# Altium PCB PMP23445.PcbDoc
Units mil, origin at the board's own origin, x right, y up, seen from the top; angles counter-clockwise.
Board outline 2350 x 1450 mil, 2 copper layers (Top Layer, Bottom Layer), stack 62 mil thick; 36 components, 16 nets, 69 pads, 11 vias.
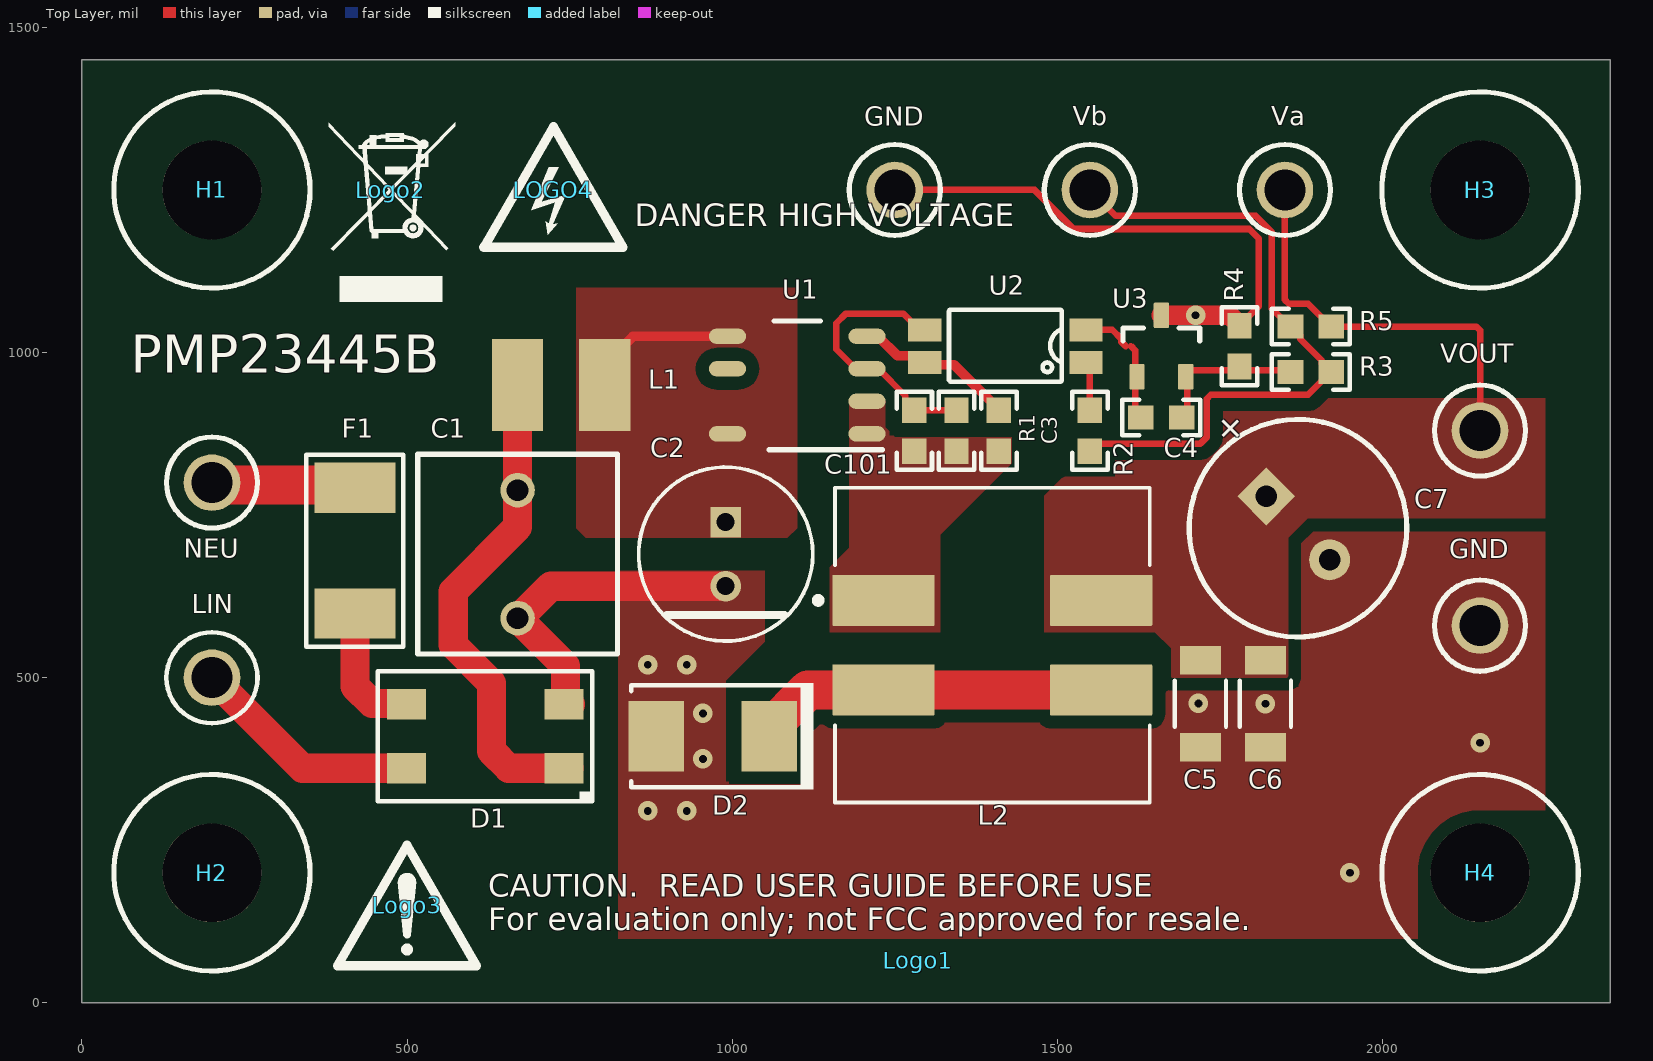
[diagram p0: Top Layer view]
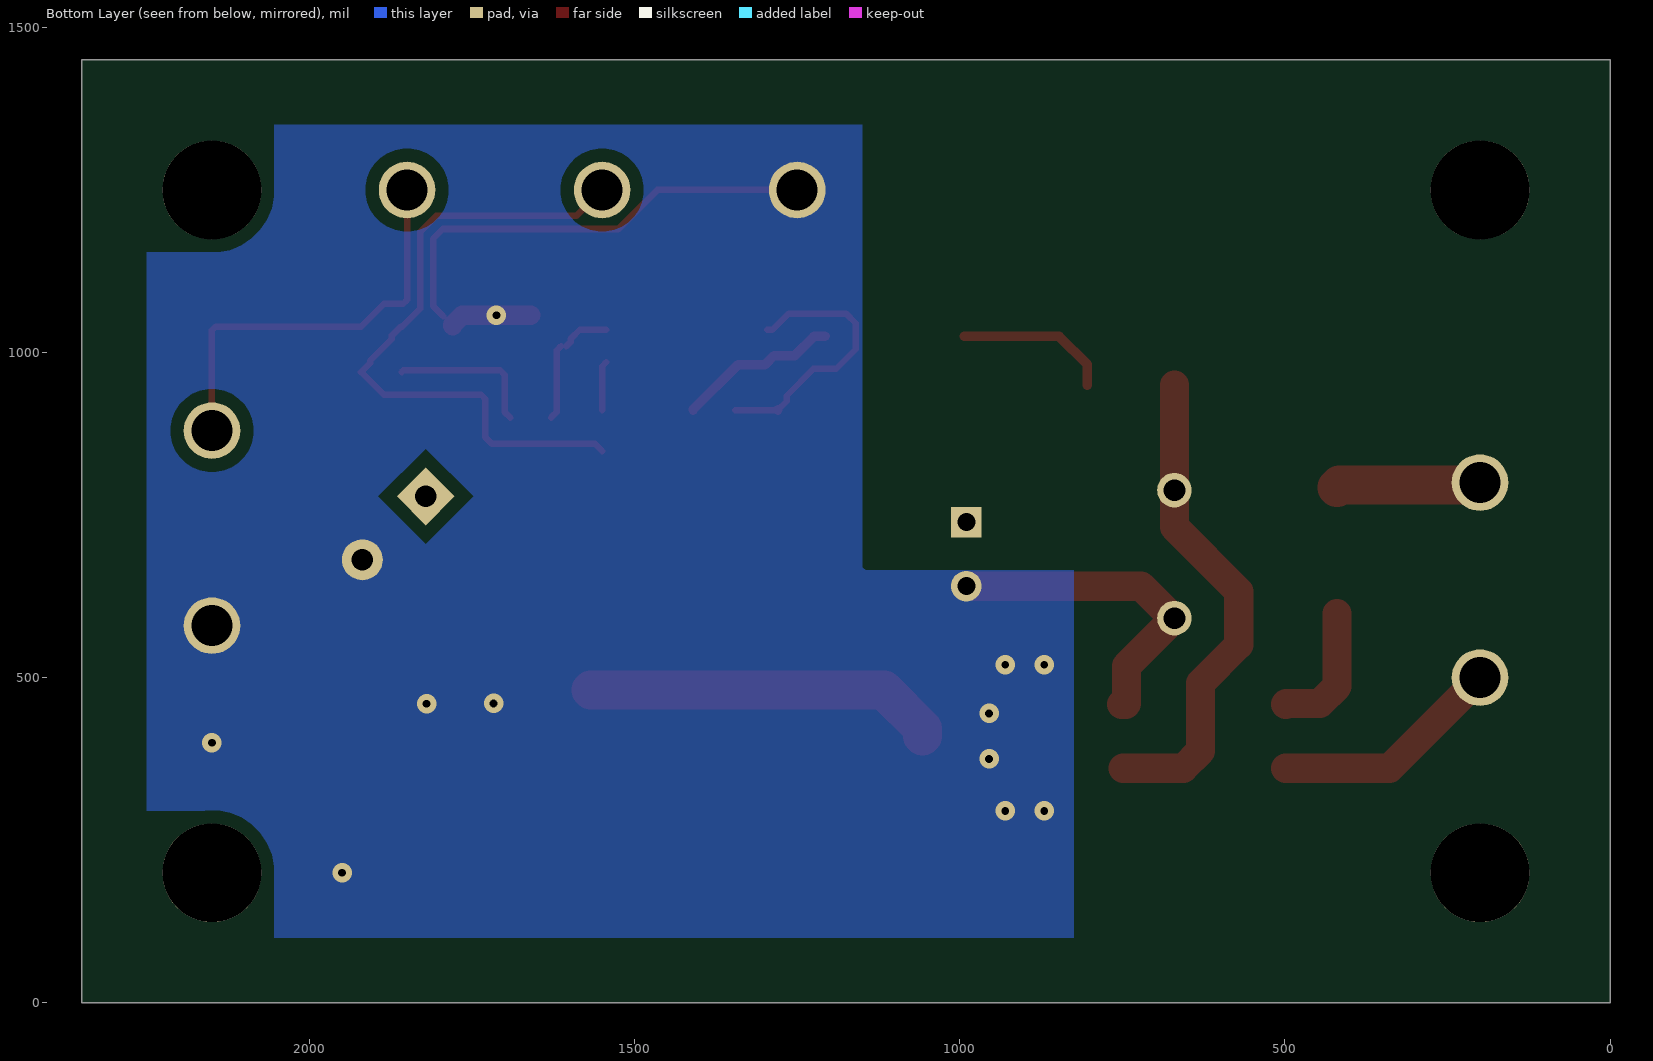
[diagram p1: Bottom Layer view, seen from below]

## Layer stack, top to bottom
Top Solder: solder mask 0.4, Solder Resist, Dk 3.5
Top Layer: signal copper 1.4
Dielectric1: core 59.2, FR-4 High Tg, Dk 4.8
Bottom Layer: signal copper 1.4
Bottom Solder: solder mask 0.4, Solder Resist, Dk 3.5

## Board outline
0,0 0,1450 2350,1450 2350,0

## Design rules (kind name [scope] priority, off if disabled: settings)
AcuteAngle [All] p1: minimum=4.50000000000000E+0001 checktracksonly=FALSE
AssemblyTestPointUsage [All] p1: valid=2
BoardOutlineClearance BoardOutlineClearance_MountingHoles [OnCopper and InComponentClass('Mounting Holes')] p1: gap=25 ignorepadtopadclearanceinfootprint=FALSE
BoardOutlineClearance BoardOutlineClearance_Poly [OnCopper and InPoly] p2: gap=25 ignorepadtopadclearanceinfootprint=FALSE
BoardOutlineClearance [OnCopper and Not InComponentClass('Logo') and not InComponentClass('FiducialMark') and not InRegion(1000,500,4000,800)] p3: gap=25 ignorepadtopadclearanceinfootprint=FALSE
Clearance Clearance_2 [InNetClass('HV') vs Not InNetClass('HV')] p1: gap=50 ignorepadtopadclearanceinfootprint=FALSE
Clearance Clearance_1 [InNetClass('MV') vs Not InNetClass('MV')] p2: gap=30 ignorepadtopadclearanceinfootprint=FALSE
Clearance Clearance_Keepouts [((IsTrack Or IsArc) And Not InPoly) And IsFree and IsKeepOut vs ((IsTrack Or IsArc) And Not InPoly) And IsFree and IsKeepOut] p3: gap=0 ignorepadtopadclearanceinfootprint=FALSE
Clearance Clearance_BoardEdge_MountingHoles [OnCopper and InComponentClass('Mounting Holes') vs IsKeepOut] p4: gap=40 ignorepadtopadclearanceinfootprint=FALSE except(0: Arc-Hole Track-Hole SMDPad-Hole THPad-Hole Via-Hole Fill-Hole Poly-Hole Region-Hole Text-Hole)
Clearance Clearance_BoardEdge_Poly [OnCopper and InPoly vs IsKeepOut] p5: gap=50 ignorepadtopadclearanceinfootprint=FALSE except(0: Arc-Hole Track-Hole SMDPad-Hole THPad-Hole Via-Hole Fill-Hole Poly-Hole Region-Hole Text-Hole)
Clearance Clearance_BoardEdge [OnCopper and Not InComponentClass('Logo') and not InComponentClass('FiducialMark') and not InRegion(1000,500,4000,800) and Not IsKeepout vs IsKeepOut] p6: gap=50 ignorepadtopadclearanceinfootprint=FALSE
Clearance Clearance_Poly [InPolygon] p7: gap=20 ignorepadtopadclearanceinfootprint=FALSE except(0: Arc-Hole Track-Hole SMDPad-Hole THPad-Hole Via-Hole Fill-Hole Poly-Hole Region-Hole Text-Hole)
Clearance [All] p8: gap=7.87 ignorepadtopadclearanceinfootprint=FALSE except(0: Arc-Hole Track-Hole SMDPad-Hole THPad-Hole Via-Hole Fill-Hole Poly-Hole Region-Hole Text-Hole)
ComponentClearance ComponentClearance_MountingHoles_FiducialMarks [InComponentClass('Mounting Holes') vs InComponentClass('FiducialMark')] p1: gap=20 collisioncheckmode=3 verticalgap=10 showdistances=FALSE
ComponentClearance ComponentClearance_Shunt [InComponentClass('Header') vs InComponentClass('Shunt')] p2: gap=0 collisioncheckmode=3 verticalgap=0 showdistances=FALSE
ComponentClearance ComponentClearance_Logo [InComponentClass('Logo')] p3: gap=5 collisioncheckmode=3 verticalgap=10 showdistances=FALSE
ComponentClearance ComponentClearance_ScrewToNut [(HasFootprint('NY PMS 440 0025 PH')) vs (HasFootprint('Keystone_1902C'))] p4: gap=20 collisioncheckmode=3 verticalgap=100000 showdistances=FALSE
ComponentClearance ComponentClearance_MountingHoles [InComponentClass('Mounting Holes')] p5: gap=20 collisioncheckmode=3 verticalgap=10 showdistances=FALSE
ComponentClearance ComponentClearance_SmallPassives [HasFootprint('0201*') or HasFootprint('0402*') or HasFootprint('0508') or HasFootprint('0603*') or HasFootprint('0612') or HasFootprint('0805*') or HasFootprint('0815*') or HasFootprint('0830*') or HasFootprint('1206*') or HasFootprint('1210*') or HasFootprint('1808*') or HasFootprint('1812*') or HasFootprint('1825*') or HasFootprint('2010*') or HasFootprint('2220*') or HasFootprint('2225*') or HasFootprint('2512*') or HasFootprint('2728*') or HasFootprint('3518*') vs HasFootprint('0201*') or HasFootprint('0402*') or HasFootprint('0508') or HasFootprint('0603*') or HasFootprint('0612') or HasFootprint('0805*') or HasFootprint('0815*') or HasFootprint('0830*') or HasFootprint('1206*') or HasFootprint('1210*') or HasFootprint('1808*') or HasFootprint('1812*') or HasFootprint('1825*') or HasFootprint('2010*') or HasFootprint('2220*') or HasFootprint('2225*') or HasFootprint('2512*') or HasFootprint('2728*') or HasFootprint('3518*')] p6: gap=20 collisioncheckmode=3 verticalgap=20 showdistances=FALSE
ComponentClearance ComponentClearance_THtoSMT [IsThruComponent vs IsSMTComponent] p7: gap=10 collisioncheckmode=3 verticalgap=10 showdistances=FALSE
ComponentClearance ComponentClearance_THtoTH [IsThruComponent vs IsThruComponent] p8: gap=10 collisioncheckmode=3 verticalgap=10 showdistances=FALSE
ComponentClearance [All] p9: gap=10 collisioncheckmode=3 verticalgap=10 showdistances=FALSE
DiffPairsRouting [All] p1: maxlimit=100 minlimit=10 mostfreqgap=10 toplayer_minwidth=15 toplayer_maxwidth=15 toplayer_prefwidth=15 bottomlayer_minwidth=15 bottomlayer_maxwidth=15 bottomlayer_prefwidth=15 maxuncoupledlength=1000
FabricationTestPointUsage TestPointUsage [All] p1: valid=2 allowmultiple=FALSE
FabricationTestpoint Testpoint [All] p1: side=3 testpointundercomponent=TRUE minsize=40 maxsize=100 preferedsize=60 minholesize=0 maxholesize=40 preferedholesize=32 testpointgrid=1 allowsidetop=TRUE allowsidebottom=TRUE usegrid=TRUE gridtolerance=0.01
FanoutControl Fanout_LCC [IsLCC] p1: bgadir=Out bgaviamode=Centered fanoutstyle=Auto fanoutdirection=Alternating viagrid=1 // Fanout_LCC (Default Rule)
FanoutControl Fanout_BGA [IsBGA] p2: bgadir=Out bgaviamode=Centered fanoutstyle=Auto fanoutdirection=Alternating viagrid=1 // Fanout_BGA (Default Rule)
FanoutControl Fanout_Default [All] p4: bgadir=Out bgaviamode=Centered fanoutstyle=Auto fanoutdirection=Alternating viagrid=1 // Fanout_Default (Default Rule)
FanoutControl Fanout_Small [(CompPinCount < 5)] p5: bgadir=Out bgaviamode=Centered fanoutstyle=Auto fanoutdirection=OutThenIn viagrid=1 // Fanout_Small (Default Rule)
Height [All] p1: minheight=0 maxheight=3000 prefheight=500
HoleSize [All] p1: absolutevalues=TRUE maxlimit=251 minlimit=7.87 maxpercent=80.000 minpercent=20.000
MinimumAnnularRing MinimumAnnularRing_ThermalPadVias [IsVia and InAnyComponent] p1: minimumring=5.91
MinimumAnnularRing [All] p2: minimumring=8
MinimumSolderMaskSliver MinimumSolderMaskSliver_Logo [InComponentClass('Logo') vs InComponentClass('Logo')] p1: minsoldermaskwidth=0.7
MinimumSolderMaskSliver [All] p2: minsoldermaskwidth=3.94
PlaneConnect [All] p1: planeconnectstyle=Direct reliefexpansion=10 reliefentries=4 reliefconductorwidth=10 reliefairgap=10
PolygonConnect PolygonConnect_15 [All vs IsNamedPolygon('C109_2') Or  IsNamedPolygon('C107_2') Or  IsNamedPolygon('HV') Or  IsNamedPolygon('Q203_5') Or  IsNamedPolygon('C107_2') Or  IsNamedPolygon('HS') Or  IsNamedPolygon('Q201_5') Or  IsNamedPolygon('Q203_5') Or  IsNamedPolygon('C106_2') Or  IsNamedPolygon('C108_2') Or  IsNamedPolygon('Vout') Or  IsNamedPolygon('Q203_5') Or  IsNamedPolygon('C108_2') Or  IsNamedPolygon('C113_2') Or  IsNamedPolygon('Q203_5') Or  IsNamedPolygon('Q201_5') Or  IsNamedPolygon('C107_2') Or  IsNamedPolygon('C102_1') Or  IsNamedPolygon('SGND') Or  IsNamedPolygon('GND') Or  IsNamedPolygon('SGND') Or  IsNamedPolygon('GND') Or  IsNamedPolygon('IN+') Or  IsNamedPolygon('IN+') Or  IsNamedPolygon('Q201_5') Or  IsNamedPolygon('Q201_5') Or  IsNamedPolygon('SGND') Or  IsNamedPolygon('SGND') Or  IsNamedPolygon('Vout') Or  IsNamedPolygon('Vout') Or  IsNamedPolygon('IN+') Or  IsNamedPolygon('GND') Or  IsNamedPolygon('IN+') Or  IsNamedPolygon('GND')] p1: connectstyle=Direct reliefconductorwidth=10 reliefentries=4 polygonreliefangle="90 Angle" airgapwidth=10
PolygonConnect PolygonConnect_14 [All vs IsNamedPolygon('C106_2') Or  IsNamedPolygon('C107_2') Or  IsNamedPolygon('C107_2') Or  IsNamedPolygon('C107_2') Or  IsNamedPolygon('C102_1') Or  IsNamedPolygon('Q203_5') Or  IsNamedPolygon('Vout') Or  IsNamedPolygon('Q203_5') Or  IsNamedPolygon('Q203_5') Or  IsNamedPolygon('Q201_5') Or  IsNamedPolygon('C108_2') Or  IsNamedPolygon('Q203_5') Or  IsNamedPolygon('HS') Or  IsNamedPolygon('HV') Or  IsNamedPolygon('C108_2') Or  IsNamedPolygon('Q201_5') Or  IsNamedPolygon('C109_2') Or  IsNamedPolygon('Q201_5') Or  IsNamedPolygon('Q201_5') Or  IsNamedPolygon('C113_2')] p2: connectstyle=Direct reliefconductorwidth=10 reliefentries=4 polygonreliefangle="90 Angle" airgapwidth=10
PolygonConnect PolygonConnect_13 [All vs IsNamedPolygon('C102_1') Or  IsNamedPolygon('HV') Or  IsNamedPolygon('C107_2') Or  IsNamedPolygon('C109_2') Or  IsNamedPolygon('C107_2') Or  IsNamedPolygon('C108_2') Or  IsNamedPolygon('C106_2') Or  IsNamedPolygon('C108_2') Or  IsNamedPolygon('C113_2') Or  IsNamedPolygon('C107_2')] p3: connectstyle=Direct reliefconductorwidth=10 reliefentries=4 polygonreliefangle="90 Angle" airgapwidth=10
PolygonConnect PolygonConnect_12 [All vs IsNamedPolygon('C107_2') Or  IsNamedPolygon('C113_2') Or  IsNamedPolygon('C106_2') Or  IsNamedPolygon('C107_2') Or  IsNamedPolygon('C107_2') Or  IsNamedPolygon('C102_1')] p4: connectstyle=Direct reliefconductorwidth=10 reliefentries=4 polygonreliefangle="90 Angle" airgapwidth=10
PolygonConnect PolygonConnect_11 [All vs IsNamedPolygon('C106_2') Or  IsNamedPolygon('C102_1') Or  IsNamedPolygon('C107_2') Or  IsNamedPolygon('C107_2') Or  IsNamedPolygon('C107_2')] p5: connectstyle=Direct reliefconductorwidth=10 reliefentries=4 polygonreliefangle="90 Angle" airgapwidth=10
PolygonConnect PolygonConnect_10 [All vs IsNamedPolygon('C106_2')] p6: connectstyle=Direct reliefconductorwidth=10 reliefentries=4 polygonreliefangle="90 Angle" airgapwidth=10
PolygonConnect PolygonConnect_9 [All vs IsNamedPolygon('C11_1') Or  IsNamedPolygon('Vin') Or  IsNamedPolygon('Vin') Or  IsNamedPolygon('5V') Or  IsNamedPolygon('D6_2') Or  IsNamedPolygon('Q3_3') Or  IsNamedPolygon('GND2') Or  IsNamedPolygon('GND2') Or  IsNamedPolygon('GND') Or  IsNamedPolygon('Q3_4') Or  IsNamedPolygon('12V5') Or  IsNamedPolygon('GND') Or  IsNamedPolygon('12V5') Or  IsNamedPolygon('D3_1')] p7: connectstyle=Direct reliefconductorwidth=10 reliefentries=4 polygonreliefangle="90 Angle" airgapwidth=10
PolygonConnect PolygonConnect_8 [All vs IsNamedPolygon('C11_1') Or  IsNamedPolygon('Vin') Or  IsNamedPolygon('12V5') Or  IsNamedPolygon('Q3_3') Or  IsNamedPolygon('GND2') Or  IsNamedPolygon('GND2') Or  IsNamedPolygon('5V') Or  IsNamedPolygon('Q3_4') Or  IsNamedPolygon('12V5')] p8: connectstyle=Direct reliefconductorwidth=10 reliefentries=4 polygonreliefangle="90 Angle" airgapwidth=10
PolygonConnect PolygonConnect_7 [All vs IsNamedPolygon('GND2') Or  IsNamedPolygon('GND2') Or  IsNamedPolygon('5V') Or  IsNamedPolygon('12V5') Or  IsNamedPolygon('12V5') Or  IsNamedPolygon('C11_1')] p9: connectstyle=Direct reliefconductorwidth=10 reliefentries=4 polygonreliefangle="90 Angle" airgapwidth=10
PolygonConnect PolygonConnect_6 [All vs IsNamedPolygon('GND2') Or  IsNamedPolygon('SGND') Or  IsNamedPolygon('GND1') Or  IsNamedPolygon('C901_1') Or  IsNamedPolygon('SGND') Or  IsNamedPolygon('GND2') Or  IsNamedPolygon('GND1')] p10: connectstyle=Direct reliefconductorwidth=10 reliefentries=4 polygonreliefangle="90 Angle" airgapwidth=10
PolygonConnect PolygonConnect_5 [All vs IsNamedPolygon('GND1') Or  IsNamedPolygon('GND1')] p11: connectstyle=Direct reliefconductorwidth=10 reliefentries=4 polygonreliefangle="90 Angle" airgapwidth=10
PolygonConnect PolygonConnect_4 [All vs IsNamedPolygon('C21_1') Or  IsNamedPolygon('C5_1') Or  IsNamedPolygon('C12_2') Or  IsNamedPolygon('C2_2') Or  IsNamedPolygon('C13_1') Or  IsNamedPolygon('C28_1') Or  IsNamedPolygon('C6_1') Or  IsNamedPolygon('GND') Or  IsNamedPolygon('GND2') Or  IsNamedPolygon('C14_1') Or  IsNamedPolygon('C13_1') Or  IsNamedPolygon('Q1_3') Or  IsNamedPolygon('C14_1') Or  IsNamedPolygon('C5_1') Or  IsNamedPolygon('GND2') Or  IsNamedPolygon('C28_1') Or  IsNamedPolygon('D5_2') Or  IsNamedPolygon('D6_2') Or  IsNamedPolygon('D2_1') Or  IsNamedPolygon('C12_2') Or  IsNamedPolygon('D2_1') Or  IsNamedPolygon('C4_1') Or  IsNamedPolygon('C4_1') Or  IsNamedPolygon('C2_2') Or  IsNamedPolygon('GND') Or  IsNamedPolygon('C33_1') Or  IsNamedPolygon('C9_1')] p12: connectstyle=Direct reliefconductorwidth=10 reliefentries=4 polygonreliefangle="90 Angle" airgapwidth=10
PolygonConnect PolygonConnect_3 [All vs IsNamedPolygon('C28_1') Or  IsNamedPolygon('C12_2') Or  IsNamedPolygon('C28_1') Or  IsNamedPolygon('C9_1') Or  IsNamedPolygon('D5_2') Or  IsNamedPolygon('C12_2') Or  IsNamedPolygon('C2_2') Or  IsNamedPolygon('C14_1') Or  IsNamedPolygon('C4_1') Or  IsNamedPolygon('C14_1') Or  IsNamedPolygon('D6_2') Or  IsNamedPolygon('GND2') Or  IsNamedPolygon('Q1_3') Or  IsNamedPolygon('C5_1') Or  IsNamedPolygon('D2_1') Or  IsNamedPolygon('C4_1') Or  IsNamedPolygon('C13_1') Or  IsNamedPolygon('C5_1') Or  IsNamedPolygon('C13_1') Or  IsNamedPolygon('C33_1') Or  IsNamedPolygon('D2_1') Or  IsNamedPolygon('GND') Or  IsNamedPolygon('GND') Or  IsNamedPolygon('GND2') Or  IsNamedPolygon('C2_2') Or  IsNamedPolygon('C6_1') Or  IsNamedPolygon('C21_1')] p13: connectstyle=Direct reliefconductorwidth=10 reliefentries=4 polygonreliefangle="90 Angle" airgapwidth=10
PolygonConnect PolygonConnect_2 [All vs IsNamedPolygon('C21_1') Or  IsNamedPolygon('C4_1') Or  IsNamedPolygon('D5_2') Or  IsNamedPolygon('C5_1') Or  IsNamedPolygon('C14_1') Or  IsNamedPolygon('C13_1') Or  IsNamedPolygon('C4_1') Or  IsNamedPolygon('C33_1') Or  IsNamedPolygon('C12_2') Or  IsNamedPolygon('D2_1') Or  IsNamedPolygon('C2_2') Or  IsNamedPolygon('C28_1') Or  IsNamedPolygon('C12_2') Or  IsNamedPolygon('D2_1') Or  IsNamedPolygon('C5_1') Or  IsNamedPolygon('Q1_3') Or  IsNamedPolygon('GND') Or  IsNamedPolygon('D6_2') Or  IsNamedPolygon('C6_1') Or  IsNamedPolygon('C2_2') Or  IsNamedPolygon('C14_1') Or  IsNamedPolygon('C28_1') Or  IsNamedPolygon('C13_1') Or  IsNamedPolygon('C9_1') Or  IsNamedPolygon('GND')] p14: connectstyle=Direct reliefconductorwidth=10 reliefentries=4 polygonreliefangle="90 Angle" airgapwidth=10
PolygonConnect PolygonConnect_1 [All vs IsNamedPolygon('C28_1') Or  IsNamedPolygon('D5_2') Or  IsNamedPolygon('C5_1') Or  IsNamedPolygon('C5_1') Or  IsNamedPolygon('D2_1') Or  IsNamedPolygon('C21_1') Or  IsNamedPolygon('C9_1') Or  IsNamedPolygon('C4_1') Or  IsNamedPolygon('C14_1') Or  IsNamedPolygon('C28_1') Or  IsNamedPolygon('C6_1') Or  IsNamedPolygon('C12_2') Or  IsNamedPolygon('C33_1') Or  IsNamedPolygon('C4_1') Or  IsNamedPolygon('C13_1') Or  IsNamedPolygon('C12_2') Or  IsNamedPolygon('D6_2') Or  IsNamedPolygon('C2_2') Or  IsNamedPolygon('C14_1') Or  IsNamedPolygon('D2_1') Or  IsNamedPolygon('C2_2') Or  IsNamedPolygon('C13_1')] p15: connectstyle=Direct reliefconductorwidth=10 reliefentries=4 polygonreliefangle="90 Angle" airgapwidth=10
PolygonConnect [All] p16: connectstyle=Direct reliefconductorwidth=10 reliefentries=4 polygonreliefangle="90 Angle" airgapwidth=10
RoutingVias ThermalPadVias [IsVia and InAnyComponent] p1: holewidth=7.87 width=19.68 viastyle="Through Hole" minholewidth=7.87 minwidth=19.68 maxholewidth=12.99 maxwidth=23.62
RoutingVias [All] p2: holewidth=16 width=34 viastyle="Through Hole" minholewidth=7.87 minwidth=20 maxholewidth=40 maxwidth=65
SilkToBoardRegionClearance [Not ((IsComment or IsDesignator) And (Hide <> 'False')) and not InRegion(1000,500,4000,800)] p1:
SilkToSilkClearance SilkToSilkClearance_Pb-FreeLogo [(HasFootprint('Pb-Free_Overlay_Medium') OR HasFootprint('Pb-Free_Overlay_Small')) vs (HasFootprint('Pb-Free_Overlay_Medium') OR HasFootprint('Pb-Free_Overlay_Small'))] p1: silktosilkclearance=0
SilkToSilkClearance [All] p2: silktosilkclearance=4
SilkToSolderMaskClearance SilkToComponentPadClearance [IsPad and InAnycomponent] p1: minsilkscreentomaskgap=5 clearancetoexposedcopper=TRUE
SilkToSolderMaskClearance "Silk to Solder Mask Opening" [All] p2: minsilkscreentomaskgap=4 clearancetoexposedcopper=FALSE
SolderMaskExpansion [All] p1: expansion=1.97 istentingtop=FALSE
Width [All] p1: maxlimit=100 minlimit=6 preferedwidth=10 checkconnectedcopper=TRUE
14 further rules are at their usual default settings.

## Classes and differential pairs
net class HV: NC NetC1_1 NetC2_2 NetD1_3 NetD1_4 NetF1_2

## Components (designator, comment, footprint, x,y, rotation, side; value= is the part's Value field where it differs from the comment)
C1 "B32529D3224J" CAPRR500W60L780T780H1300 670,690 r270 top value=0.22uF
C2 "ECA2EM2R2" FP-ECA2EM2R2_RADIAL-MFG 990,690 r90 top value=2.2µF
C3 "GRM188R71C104KA01D" 0603 1410,880 r270 top value=0.1uF
C4 "GRM188R71C104KA01D" 0603 1660,900 r0 top value=0.1uF
C5 "GRM31CR60J107ME39L" 1206_180 1720,460 r270 top value=100uF
C6 "GRM31CR60J107ME39L" 1206_180 1820,460 r270 top value=100uF
C7 "ECA-0JHG102" NHG_800x1150 1870,730 r315 top value=1000uF
C101 "GRM188R71C333KA01D" 0603 1280,880 r270 top value=0.033uF
D1 "HD02-T" MiniDIP 620,410 r180 top value=200V
D2 "MBRS3200T3G" SMB 970,410 r180 top value=200V
F1 "0454001.MR" SloBlo452 420,695.47 r90 top
GND "5011" Keystone5011 2150,580 r0 top
GND "5011" Keystone5011 1250,1250 r0 top
H1 "4824" KEYSTONE_4824 200,1250 r0 top
H2 "4824" KEYSTONE_4824 200,200 r0 top
H3 "4824" KEYSTONE_4824 2150,1250 r0 top
H4 "4824" KEYSTONE_4824 2150,200 r0 top
L1 "744045391" WE-LQ_1812 736.93,950 r0 top
L2 "MSD1278T-224KLD" FP-MSD1278T-224KLD_SMT_IND_12MM3_12MM3-MFG 1400,550 r0 top
LIN "5125" Keystone5125 200,500 r0 top
Logo1 "FCC disclaimer" FCC_disclaimer 1285.77,65 r0 top
Logo2 "WEEE logo" WEEE_Minimum 475,1250 r0 top
Logo3 "CAUTION.  READ USER GUIDE BEFORE USE" IEC_Caution_Small 500,150 r0 top
LOGO4 "DANGER HIGH VOLTAGE" IEC_HighVoltage_Small 725,1250 r0 top
NEU "5127" Keystone5127 200,800 r0 top
R1 "CRCW06034K99FKEAC" 0603 1345,880 r90 top value=4.99k
R2 "CRCW06031K00FKEA" 0603 1550,880 r270 top value=1.00k
R3 "CRCW060342K2FKEA" 0603 1890,970 r0 top value=42.2k
R4 "CRCW060324K9FKEA" 0603 1780,1010 r270 top value=24.9k
R5 "CRCW060310R0FKEA" 0603 1890,1040 r0 top value=10.0
U1 "UCC28881DR" D0007A_N 1100,950 r180 top
U2 "TCMT1107" SOP-4 1420,1010 r180 top
U3 "TLVH432BCDBZR" DBZ0003A_N 1660,1010 r90 top
Va "5010" Keystone5010 1850,1250 r0 top
Vb "5012" Keystone5012 1550,1250 r0 top
VOUT "5010" Keystone5010 2150,880 r0 top

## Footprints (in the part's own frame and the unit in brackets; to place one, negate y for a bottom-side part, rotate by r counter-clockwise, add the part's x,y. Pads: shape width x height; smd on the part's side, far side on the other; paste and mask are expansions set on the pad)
0603 [mm] "0603 from SM-752 data"
  rect 1x0.95 smd: 1(-0.8,0) 2(0.8,0)
  silkscreen extent -1.52,-0.69 1.52,0.69, body extent -0.87,-0.47 0.87,0.47, height 1
1206_180 [mm] "1206_180"
  rect 1.1x1.6 smd: 1(-1.7,0) 2(1.7,0)
  silkscreen extent -0.9,-1 0.9,1, body extent -1.75,-0.95 1.75,0.95, height 1.8
CAPRR500W60L780T780H1300 [mm] "EPCOS"
  round 1.35 hole 0.85: 1(-2.5,0) 2(2.5,0)
  silkscreen extent -3.9,-3.9 3.9,3.9, body extent -3.9,-3.9 3.9,3.9, height 13
D0007A_N [mm] "SOIC, 7-Leads, Body 4.9x3.9mm, Pitch 1.27mm, IPC Medium Density"
  oval 1.45x0.6 smd: 1(-2.725,1.905) 2(-2.725,0.635) 3(-2.725,-0.635) 4(-2.725,-1.905) 5(2.725,-1.905) 6(2.725,-0.635) 8(2.725,1.905)
  silkscreen extent -3.32,-2.5 1.1,2.52, body extent -3.01,-2.45 3.01,2.45, height 1.75
DBZ0003A_N [mm] "SOT23, 3-Leads, Body 2.9x1.3mm, Pitch 0.95mm, Lead Span 2.4mm, IPC Medium Density"
  rrect17% 1x0.6 smd: 1(-1.2,0.95) 2(-1.2,-0.95) 3(1.2,0)
  silkscreen extent 0.2,-1.5 0.7,1.5, body extent -1.26,-1.46 1.26,1.46, height 0.98
FCC_disclaimer [mil]
FP-ECA2EM2R2_RADIAL-MFG [mm]
  round 1.2 hole 0.7 paste-2539.97 mask+0: 1(-1.25,0)
  rect 1.2x1.2 hole 0.7 paste-2539.97 mask+0: 2(1.25,0)
  silkscreen extent -3.4,-3.4 3.4,3.4, body extent -3.5,-3.5 3.5,3.5, height 0.25
FP-MSD1278T-224KLD_SMT_IND_12MM3_12MM3-MFG [mm]
  rrect5% 4x2 smd paste+0 mask+0: 1(-4.25,1.75) 2(-4.25,-1.75) 3(4.25,-1.75) 4(4.25,1.75)
  silkscreen extent -6.92,-6.15 6.15,6.15, body extent -6.35,-6.25 6.35,6.25, height 0.25
IEC_Caution_Small [mil]
  silkscreen extent -107,-93 107,92
IEC_HighVoltage_Small [mil]
  silkscreen extent -107,-88 107,97
Keystone5010 [mil] "Keystone Multipurpose loops"
  round 87 hole 63: 1(0,0)
  silkscreen extent -70,-70 70,70, body extent -63,-63 63,62, height 319
Keystone5011 [mil] "Keystone Multipurpose loops"
  round 87 hole 63: 1(0,0)
  silkscreen extent -70,-70 70,70, body extent -63,-63 63,62, height 319
Keystone5012 [mil] "Keystone Multipurpose loops"
  round 87 hole 63: 1(0,0)
  silkscreen extent -70,-70 70,70, body extent -63,-63 63,62, height 319
Keystone5125 [mil] "Keystone Multipurpose loops"
  round 87 hole 63: 1(0,0)
  silkscreen extent -70,-70 70,70, body extent -63,-63 63,62, height 319
Keystone5127 [mil] "Keystone Multipurpose loops"
  round 87 hole 63: 1(0,0)
  silkscreen extent -70,-70 70,70, body extent -63,-63 63,62, height 319
KEYSTONE_4824 [mil] "HEX STANDOFF 6-32 NYLON 1-1/2\""
  round 1 on Mech3: 0(0,0)
  round 152 hole 152 unplated: MH(0,0)
  silkscreen extent -151,-151 151,151, body extent -144,-125 144,125, height 1500
MiniDIP [mm] "Land pattern created based on STEP model."
  rect 1.52x1.2 smd: 1(-3.075,1.25) 2(-3.075,-1.25) 3(3.075,-1.25) 4(3.075,1.25)
  silkscreen extent -4.19,-2.54 4.19,2.54, body extent -3.5,-2.45 3.5,2.45, height 2.75
NHG_800x1150 [mm] "Panasonic"
  rect 1.6x1.6 hole 0.838: 1(-1.75,0)
  round 1.6 hole 0.838: 2(1.75,0)
  silkscreen extent -4.25,-4.25 4.25,4.25, body extent -4.22,-4.24 4.24,4.24, height 12.51
SloBlo452 [mm] "Littelfuse 452/4 Fuses, recommended land pattern"
  rect 1.96x3.15 smd: 1(-2.455,0) 2(2.455,0)
  silkscreen extent -3.75,-1.88 3.75,1.9, body extent -3.05,-1.35 3.05,1.34, height 2.69
SMB [mil] "Molded Diode, 2-Leads, Body 5.4x3.6mm, IPC Medium Density, based on OnSemi component dimensions"
  rect 85x107.99 smd: 1(-87.01,0) 2(87.01,0)
  silkscreen extent -155,-82 125,82, body extent -106,-71 106,71, height 91
SOP-4 [mm] "Vishay Half Pitch Mini-Flat Package"
  rect 1.3x0.9 smd: 1(-3.15,0.635) 2(-3.15,-0.635) 3(3.15,-0.635) 4(3.15,0.635)
  silkscreen extent -2.2,-1.41 2.2,1.39, body extent -3.5,-1.4 3.5,1.4, height 2.12
WE-LQ_1812 [mm] "SMT Inductor, body 4.5x3.2mm"
  rect 2x3.6 smd: 1(-1.7,0) 2(1.7,0)
  body extent -2.25,-1.6 2.25,1.6, height 2.59
WEEE_Minimum [mil] "WEEElie bin"
  silkscreen extent -95,-172 99,104

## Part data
C1: library part CMP-0012341-3, "CAP, Film, 0.22 uF, 250 V, +/- 5%, TH", Cap_Case=7.8x13x7.8, Manufacturer=TDK, Supplier Part Number 1=495-1204-ND, Tolerance_%=5%, Value1=Unknown, Value2=250V, ValueDisplayed=0.22uF
C2: library part CMP-0120186-1, "Aluminum Electrolytic Capacitors (Radial Lead Type) 2.2uF ±20% 250V", Leakage Current=43uA, Manufacturer=Panasonic, Operating Temperature Range="-25°C to +85°C", Tolerance_%=20%, ValueDisplayed=2.2uF
C3 C4: library part CMP-0007378-5, "CAP, CERM, 0.1 uF, 16 V, +/- 10%, X7R, 0603", Cap_Case=0603, Manufacturer=MuRata, Supplier Part Number 1=490-1532-1-ND, TempCo=X7R, Tolerance_%=10%, Value1=Unknown, Value2=16V, ValueDisplayed=0.1uF
C5 C6: library part CMP-0008934-2, "CAP, CERM, 100 uF, 6.3 V, +/- 20%, X5R, 1206", Cap_Case=1206, Manufacturer=MuRata, Supplier Part Number 1=490-4539-1-ND, TempCo=X5R, Tolerance_%=20%, Value1="0.003 ohm", Value2=6.3V, ValueDisplayed=100uF
C7: library part CMP-0010321-1, "CAP, AL, 1000 uF, 6.3 V, +/- 20%, TH", Cap_Case=8x11.5mm, Manufacturer=Panasonic, Supplier Part Number 1=P5509-ND, Tolerance_%=20%, Value1=Unknown, Value2=6.3V, ValueDisplayed=1000uF
C101: library part CMP-0007392-5, "CAP, CERM, 0.033 uF, 16 V, +/- 10%, X7R, 0603", Cap_Case=0603, Manufacturer=MuRata, Supplier Part Number 1=490-1528-1-ND, TempCo=X7R, Tolerance_%=10%, Value1=Unknown, Value2=16V, ValueDisplayed=0.033uF
D1: library part CMP-0029216-3, "Diode, Switching-Bridge, 200 V, 0.8 A, MiniDIP", Manufacturer="Diodes Inc.", Value1=0.8A, Value2=1V
D2: library part CMP-0028599-2, "Diode, Schottky, 200 V, 3 A, SMB", Manufacturer="ON Semiconductor", Value1=3A, Value2=0.84V
F1: library part CMP-0003483-2, "Fuse, 1 A, 125VAC/VDC, SMD", Irating_A=1A, Manufacturer=Littelfuse, Supplier Part Number 1=F3144CT-ND
GND GND: library part CMP-0055148-2, "Test Point, Multipurpose, Black, TH", Color=Black, Manufacturer="Keystone Electronics", Supplier Part Number 1=36-5011-ND
H1 H2 H3 H4: library part CMP-0003690-1, Manufacturer=Keystone, Supplier Part Number 1=36-4824-ND
L1: library part CMP-0073803-1, "WE-LQ SMT Power Inductor, size 1812, 390uH, 0.11A", Case/Size Code=1812, DC Resistance Max=13Ohm, Inductance=390uH, Manufacturer="Wurth Elektronik", Operating Temperature Max=125°C, Operating Temperature Min=-40°C, Rated Current=0.11A, Saturation Current=0.27A, Self Resonant Frequency=5MHz
L2: library part CMP-0120188-1, "Coupled Inductors 220uH Shld 10% 1.05A 690mOhms AECQ2", Manufacturer=Coilcraft, Mouser Part Number=994-MSD1278T-224KLD, Operating Temperature Range=to, Self Resonant Frequency=3.4MHz, Test Frequency=100kHz, Tolerance_%=10%
LIN: library part CMP-0055157-1, "Test Point, Multipurpose, Brown, TH", Color=Brown, Manufacturer=Keystone, Supplier Part Number 1=36-5125-ND
Logo1: library part CMP-0074847-1, "FCC_disclaimer"
Logo2: library part CMP-0074769-1
Logo3: library part CMP-0074836-1, "IEC 61010-1 Caution Warning"
LOGO4: library part CMP-0074835-1, "IEC 61010-1 High Voltage Warning"
NEU: library part CMP-0055156-1, "Test Point, Multipurpose, Blue, TH", Color=Blue, Manufacturer=Keystone, Supplier Part Number 1=36-5127-ND
R1: library part CMP-0082533-1, "RES, 4.99 k, 1%, 0.1 W, 0603", Manufacturer=Vishay-Dale, Power_W=100mW, Supplier Part Number 1=541-3985-1-ND, TempCo="100 ppm/C", Tolerance_%=1%, Value2=0.1W, Value_Code=4k99, ValueDisplayed=4.99k
R2: library part CMP-0022109-5, "RES, 1.00 k, 1%, 0.1 W, AEC-Q200 Grade 0, 0603", Manufacturer=Vishay-Dale, Power_W=100mW, Supplier Part Number 1=541-1.00KHCT-ND, TempCo="100 ppm/C", Tolerance_%=1%, Value2=0.1W, Value_Code=1k00, ValueDisplayed=1.00k
R3: library part CMP-0022418-4, "RES, 42.2 k, 1%, 0.1 W, AEC-Q200 Grade 0, 0603", Manufacturer=Vishay-Dale, Power_W=100mW, Supplier Part Number 1=541-42.2KHCT-ND, TempCo="100 ppm/C", Tolerance_%=1%, Value2=0.1W, Value_Code=42k2, ValueDisplayed=42.2k
R4: library part CMP-0022237-4, "RES, 24.9 k, 1%, 0.1 W, AEC-Q200 Grade 0, 0603", Manufacturer=Vishay-Dale, Power_W=100mW, Supplier Part Number 1=541-24.9KHCT-ND, TempCo="100 ppm/C", Tolerance_%=1%, Value2=0.1W, Value_Code=24k9, ValueDisplayed=24.9k
R5: library part CMP-0022003-4, "RES, 10.0, 1%, 0.1 W, AEC-Q200 Grade 0, 0603", Manufacturer=Vishay-Dale, Power_W=100mW, Supplier Part Number 1=541-10.0HCT-ND, TempCo="100 ppm/C", Tolerance_%=1%, Value2=0.1W, Value_Code=10R0, ValueDisplayed=10.0
U1: library part CMP-0074092-2, "700-V Lowest Quiescent Current Off-Line Switcher, D0007A (SOIC-7)", Alternate Manufacturer="Texas Instruments", Alternate PartNumber=UCC28881D
U2: library part CMP-0006166-3, "Optocoupler, 3.75 kV, 80-160% CTR, SMT", Manufacturer=Vishay-Semiconductor, Supplier Part Number 1=TCMT1107CT-ND, Voltage_Isolation_Vrms=3.75kV
U3: library part CMP-0033010-1, "Low-Voltage Adjustable Precision Shunt Regulator, 129 ppm / degC, 80 mA, 0 to 70 degC, 3-pin SOT-23 (DBZ), Green (RoHS & no Sb/Br)", Manufacturer="Texas Instruments", Rating=Catalog, Temp Coeff(Max)(ppm/ degree C)=129
Va VOUT: library part CMP-0055147-2, "Test Point, Multipurpose, Red, TH", Color=Red, Manufacturer="Keystone Electronics", Supplier Part Number 1=36-5010-ND
Vb: library part CMP-0055149-2, "Test Point, Multipurpose, White, TH", Color=White, Manufacturer="Keystone Electronics", Supplier Part Number 1=36-5012-ND

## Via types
v1: diameter 30, hole 12, Top Layer to Bottom Layer, tented top, 11 vias

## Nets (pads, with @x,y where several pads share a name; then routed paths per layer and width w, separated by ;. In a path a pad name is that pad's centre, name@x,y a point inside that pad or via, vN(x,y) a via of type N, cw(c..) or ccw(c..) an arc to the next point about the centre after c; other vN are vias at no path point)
FB: C101.1 R1.2 U1.3 U2.3 | length 421.3
  Top Layer w10: U2.3 1288.11,1035 1263.11,1060 1175,1060 1160,1045 1160,1005 1190,975 1224.99,975 1266.3,933.69 1266.3,925.2 C101.1 R1.2
GND: C1.2 C2.1 C5.2 C6.2 C7.2 D1.2 D2.2 GND.1 R4.1 U3.3 | length 1353.3
  Top Layer w10: GND.1@1250,1250 1465,1250 1525,1190 1795,1190 1810,1175 1810,1071.5 R4.1@1794.69,1056.18
  Top Layer w30: U3.3 1765.24,1057.24 1780,1042.48 R4.1
  Top Layer w45: D1.2@751.06,459.21 744.76,459.21 743.64,460.33 743.64,517.93 C1.2 672.21,591.57 721.42,640.79 C2.1
  other v1: 1950,200 870,295 930,295 955,375 2150,400 955,445 1716.89,460.33 1820,460 870,520 930,520 1712.62,1057.24
NC: U1.6
NetC1_1: C1.1 D1.1 L1.1 | length 757.8
  Top Layer w45: L1.1 670,731.69 570.93,632.61 570.93,550.54 630,491.46 630,387.15 656.36,360.79 D1.1@748.48,360.79
NetC2_2: C2.2 L1.2 U1.5 U1.8 | length 238.4
  Top Layer w15: L1.2 803.86,981.5 847.36,1025 U1.5
NetC3_2: C3.2 C101.2 L2.1 R1.1 U1.1 U1.2
NetC4_1: C4.1 U2.2 U3.1 | length 190.8
  Top Layer w10: U2.2 1584.61,1035 1598.07,1021.54 1598.07,1016.81 1604.88,1010 ; 1612.76,1010 1613.19,1010 1620,1003.19 1620,908.5 C4.1
NetC4_2: C4.2 R3.1 R4.2 U3.2 | length 231.7
  Top Layer w10: C4.2 1700,908.5 1700,965.79 1706.81,972.6 1780,972.6 1855.91,972.6 R3.1
NetD1_3: D1.3 F1.1 | length 202.4
  Top Layer w45: F1.1 420,486.7 446.36,460.33 497.81,460.33 D1.3
NetD1_4: D1.4 LIN.1 | length 356.6
  Top Layer w45: LIN.1 339.21,360.79 D1.4
NetD2_1: D2.1 L2.2 L2.3 | length 546.5
  Top Layer w60: D2.1 1057.01,421.5 1116.61,481.1 L2.2 L2.3
NetF1_2: F1.2 NEU.1 | length 223.3
  Top Layer w60: NEU.1 203.94,796.06 416.06,796.06 F1.2
NetR2_1: R2.1 U2.1 | length 76
  Top Layer w10: U2.1 1550,979.02 R2.1
NetR2_2: R2.2 R3.2 R5.1 Vb.1 | length 1017
  Top Layer w10: R2.2 1561.5,860 1720,860 1730,870 1730,929.14 1735.86,935 1885.51,935 R3.2@1920.51,970 ; Vb.1 1590,1210 1805,1210 1830,1185 1830,1067.52 1857.52,1040 R5.1 1859.49,1040 1873.19,1026.3 1873.19,1021.1 1906.81,987.48 1906.81,983.7 R3.2@1920.51,970 ; R3.2 R3.2@1920.51,970
VDD: C3.1 U1.4 U2.4 | length 250.3
  Top Layer w15: U1.4 1224.02,1025 1253.8,995.22 1285.77,995.22 1299.78,981.21 1341.27,981.21 1410,912.48 C3.1
VOUT: C5.1 C6.1 C7.1 L2.4 R5.2 Va.1 VOUT.1 | length 642.6
  Top Layer w10: Va.1 1850,1080.86 1855.86,1075 1885.51,1075 1920.51,1040 R5.2 2144.14,1040 2150,1034.14 VOUT.1
pads on no net: H1.0 H1.MH H2.0 H2.MH H3.0 H3.MH H4.0 H4.MH

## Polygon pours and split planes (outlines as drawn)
GND on Top Layer "TOP_LAYER_GND_P004" (solid, remove dead copper, pour order 4): 990,495 1050,555 1050,665 825,665 825,98.89 2250,98.89 2250,743.89 1885,743.89 1855,713.89 1855,498.89 1203.89,498.89 1045,340 990,340
VOUT on Top Layer "TOP_LAYER_VOUT_P002" (solid, remove dead copper, pour order 2): 1480,570 1650,570 1675,545 1675,500 1855,500 1855,715 1885,745 2250,745 2250,930 1520,930 1520,820 1480,780
NetC3_2 on Top Layer "TOP_LAYER_NETC3_2_P001" (solid, remove dead copper, pour order 1): 1180,925 1235,925 1235,885 1250,870 1430,870 1430,830 1320,720 1320,570 1150,570 1150,670 1180,700
NetC2_2 on Top Layer "TOP_LAYER_NETC2_2_P000" (solid, remove dead copper, pour order 0): 760,730 760,1030 760,1100 1100,1100 1100,730 1085,715 775,715
GND on Bottom Layer "BOTTOM_LAYER_GND_P003" (solid, remove dead copper, pour order 3): 1145,665 825,665 825,100 2250,100 2250,1350 1150,1350 1150,670

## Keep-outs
Keep-Out Layer:
  text ".Layer_Name" at 577,-858.49 h60

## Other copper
Top Layer:
  pour cut-out: 2054,209.46 2140.54,296 2255.46,296 2054,94.54
  text ".Layer_Name" at 577,-858.49 h60
Bottom Layer:
  pour cut-out: 2140.82,1154.27 2054.27,1240.82 2054.27,1355.73 2255.73,1154.27
  pour cut-out: 2054.27,209.18 2140.82,295.73 2255.73,295.73 2054.27,94.27
  text ".Layer_Name" at 577,-858.49 h60

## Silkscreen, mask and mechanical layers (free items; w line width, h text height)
Top Overlay:
  text "PMP23445B" at 75,950 h100
  text ".Layer_Name" at 577,-858.49 h60
Bottom Overlay:
  text ".Layer_Name" at 577,-858.49 h60
Top Paste:
  text ".Layer_Name" at 577,-858.49 h60
Bottom Paste:
  text ".Layer_Name" at 577,-858.49 h60
Top Solder:
  text ".Layer_Name" at 577,-858.49 h60
  text ".Layer_Name" at 577,-858.49 h60
Bottom Solder:
  text ".Layer_Name" at 577,-858.49 h60
Drill Guide:
  text ".Layer_Name" at 577,-858.49 h60
M1 Board Outline:
  the board outline again, w10
  text ".Layer_Name" at 577,-858.49 h60
M2 Board Dimensions:
  rectangle: 0,-275 125,-150
  rectangle: 125,-400 500,-275
  lines w7: 0,-275 1000,-275 ; 125,-400 125,-150 ; 250,-400 250,-150 ; 500,-400 500,-150 ; 750,-400 750,-150 ; 0,-400 1000,-400 1000,-150 0,-150 0,-400
  text ".Layer_Name" at 577,-858.49 h60
M3 3D STEP Top:
  text ".Layer_Name" at 577,-858.49 h60
M4 3D STEP Bottom:
  text ".Layer_Name" at 577,-858.49 h60
M5 Assembly Top:
  lines w10: -292,-930.17 6308,-930.17 ; -292,-726.83 6310,-726.83 ; -292,-523.5 -292,-1133.5 3713,-1133.5 6310,-1133.5 6310,-523.5 -291.5,-523.5 -291.5,-1133.5 1284,-1133.5 ; 2173,-1133.5 2173,-523.5 ; 3440,-726.83 3440,-523.5 ; 4280,-726.83 4280,-523.5 ; 4902,-1140 4902,-937.17
  text "COMPONENTS MARKED 'DNP' SHOULD NOT BE POPULATED." at 1153.5,-318.5 h60
  text "ASSEMBLY VARIANT:" at 1153,-434 h60
  text ".VariantName" at 2189,-434 h60
  text "PCB VIEWED FROM TOP SIDE" at -228.5,-655.67 h60
  text "BOARD #:" at 2248,-655.67 h60
  text ".PRJ_Number" at 2793.5,-655.67 h60
  text "REV:" at 3638,-655.67 h60
  text ".PCB_Rev" at 3929.5,-655.67 h60
  text "SVN REV:" at 4476,-655.67 h60
  text ".VersionControl_RevNumber" at 4982,-655.67 h60
  text "TID #:" at 2248,-859 h60
  text ".TID" at 2793.5,-859 h60
  text "PLOT NAME =" at -228.5,-1064.34 h60
  text ".plot_File_Name" at 577,-1064.34 h60
  text "GENERATED    :" at 2250,-1064.34 h60
  text ".Print_Date" at 3119.5,-1064.34 h60
  text ".Print_Time" at 3848.5,-1064.34 h60
  text "TEXAS INSTRUMENTS" at 5113,-1064.34 h60
M6 Assembly Bottom:
  lines w10: -292.5,-727.33 6309.5,-727.33 ; -290.5,-930.67 6309.5,-930.67 ; 1115.5,-1140.5 1115.5,-937.67 ; 1737.5,-727.33 1737.5,-524 ; 2577.5,-727.33 2577.5,-524 ; 3844.5,-1134 3844.5,-524 ; 4733.5,-1134 6309,-1134 6309,-524 -292.5,-524 -292.5,-1134 2304.5,-1134 6309.5,-1134 6309.5,-524
  text "COMPONENTS MARKED 'DNP' SHOULD NOT BE POPULATED." at 6102,-318 h60
  text ".VariantName" at 5058,-434 h60
  text "ASSEMBLY VARIANT:" at 6097,-434 h60
  text ".VersionControl_RevNumber" at 1035.5,-656.17 h60
  text "SVN REV:" at 1541.5,-656.17 h60
  text ".PCB_Rev" at 2088,-656.17 h60
  text "REV:" at 2379.5,-656.17 h60
  text ".PRJ_Number" at 3224,-656.17 h60
  text "BOARD #:" at 3769.5,-656.17 h60
  text "PCB VIEWED FROM BOTTOM SIDE" at 6246,-656.17 h60
  text ".TID" at 3224,-859.5 h60
  text "TID #:" at 3769.5,-859.5 h60
  text "TEXAS INSTRUMENTS" at 904.5,-1064.84 h60
  text ".Print_Time" at 2169,-1064.84 h60
  text ".Print_Date" at 2898,-1064.84 h60
  text "GENERATED    :" at 3767.5,-1064.84 h60
  text ".plot_File_Name" at 5440.5,-1064.84 h60
  text "PLOT NAME =" at 6246,-1064.84 h60
M9 Title Sheet:
  drawing of 57 lines, arcs and shapes, not listed
  text "1" at 739.84,8036.5 h70
  text "2" at 3235.5,8036.5 h70
  text "3" at 5724.84,8036.5 h70
  text "4" at 8231.51,8036.5 h70
  text "5" at 10730.5,8036.5 h70
  text "6" at 13235.5,8036.5 h70
  text "A" at -416.5,6893.5 h70
  text "A" at 14383.5,6893.5 h70
  text "B" at -416.5,4513.5 h70
  text "B" at 14383.5,4513.5 h70
  text "C" at -416.5,2138.5 h70
  text "C" at 14383.5,2138.5 h70
  text "PROJECT TITLE:" at 11343.5,277.5 h45
  text ".PRJ_Title" at 11393.5,144.17 h70
  text "DESIGNED FOR:" at 11343.5,-23.5 h45
  text ".PRJ_Customer" at 11393.5,-163.5 h70
  text "D" at -416.5,-231.5 h70
  text "D" at 14383.5,-231.5 h70
  text "FILE NAME:" at 11343.5,-323.5 h45
  text ".PCB_File_Name_No_Path" at 11393.5,-443.5 h70
  text "Texas Instruments (TI) and/or its licensors do not warrant the accuracy or completeness of this specification" at 6374,-605.34 h45
  text "ENGINEER:" at 11343.5,-613.5 h45
  text "LAYOUT BY:" at 12848.5,-613.5 h45
  text "or any information contained therein. TI and/or its licensors do not warrant that this design will meet" at 6329.01,-718 h45
  text ".PRJ_Engineer" at 11393.5,-768.49 h70
  text ".PCB_Layout" at 12899,-768.49 h70
  text "the specifications, will be suitable for your application or fit for any particular purpose, or will operate in" at 6329.01,-830.67 h45
  text ".Layer_Name" at 577,-858.49 h60
  text "ALTIUM DESIGNER VERSION:" at 12848.5,-923.5 h45
  text "an implementation. TI and/or its licensors do not warrant that the design is production worthy. You should" at 6329.01,-943.33 h45
  text "completely validate and test your design implementation to confirm the system functionality for your application." at 6374,-1056 h45
  text ".print_Scale" at 11393.5,-1056.83 h70
  text ".Application_BuildNumber" at 12899,-1056.83 h70
  text "1" at 739.84,-1263.5 h70
  text "2" at 3235.5,-1263.5 h70
  text "3" at 5724.84,-1263.5 h70
  text "4" at 8231.51,-1263.5 h70
  text "5" at 10730.5,-1263.5 h70
  text "6" at 13235.5,-1263.5 h70
M10 Fab Notes:
  drawing of 189 lines, arcs and shapes, not listed
  text "DESIGN INFORMATION" at 12382.02,6356.17 h60
  text "MIN. TRACK WIDTH:" at 11737.46,6224.05 h60
  text "8" at 12833.7,6224.05 h60
  text "MIL" at 12988.46,6224.05 h60
  text "7.874" at 12667.32,6102.36 h60
  text "MIN. CLEARANCE:" at 11737.46,6099.92 h60
  text "MIL" at 12988.46,6099.92 h60
  text "MIN. VIA PAD SIZE:" at 11737.46,5975.8 h60
  text "24" at 12803.71,5975.8 h60
  text "MIL" at 12988.46,5975.8 h60
  text "0.05mm (2MIL)" at 12432.46,5845.9 h60
  text "MINIMUM ANNULAR RING" at 11408.23,5837.67 h60
  text "EXTERNAL" at 13140.46,5837.67 h60
  text "PER" at 11608.23,5727.55 h60
  text "IPC-D-275 CLASS 2 LEVEL C" at 11828.23,5727.54 h60
  text "MIL, HOLES" at 13316.46,5627.07 h60
  text "+/-" at 12924,5618.48 h60
  text "+/-" at 13778,5618.48 h60
  text "REGISTRATION TOLERANCES:" at 11408.23,5617.42 h60
  text "METAL" at 12608,5617.42 h60
  text "5" at 13184.2,5617.42 h60
  text "3" at 14017.2,5617.42 h60
  text "MIL" at 14133.46,5617.42 h60
  text "HOLE SIZE TOLERANCE (UNLESS OTHERWISE SPECIFIED):" at 11408.23,5519.1 h60
  text "+/-" at 13778,5516.23 h60
  text "3" at 14017.2,5515.17 h60
  text "MIL" at 14133.46,5515.17 h60
  text "MATERIAL:" at 11333.46,5377.52 h60
  text "FR-4 High Tg" at 12319.9,5249 h60
  text "X" at 12175.46,5241.01 h60
  text "FR-4" at 11754.46,5236.49 h60
  text "OTHER" at 13242.46,5236.49 h60
  text "62 MIL (1.6mm) +/-10%" at 12074.56,5093.46 h60
  text "X" at 11954.46,5091.01 h60
  text "THICKNESS:" at 11408.23,5085.24 h60
  text "OTHER" at 13359.46,5085.24 h60
  text "TOLERANCE:" at 11408.23,4946.92 h60
  text "X" at 12256.46,4946.92 h60
  text "ANSI IPC-6012 TYPE 3 CLASS 2" at 12434.48,4946.92 h60
  text "OTHER +/-" at 12434.46,4802.73 h60
  text "BOW & TWIST:" at 11408.23,4657.54 h60
  text "X" at 12256.46,4657.54 h60
  text "ANSI IPC-6012 TYPE 3 CLASS 2" at 12434.48,4657.54 h60
  text "OTHER +/-" at 12434.46,4510.85 h60
  text "DRILLING:" at 11333.46,4380.23 h60
  text "NC_DRILL FILES" at 13094.46,4275.04 h60
  text "REFERENCE:" at 11408.23,4271.1 h60
  text "X" at 12065.46,4271.01 h60
  text "AS SHOWN" at 12243.46,4271.1 h60
  text "X" at 12966.46,4271.1 h60
  text "OTHER" at 13392.46,4128.85 h60
  text "PTH COPPER THICKNESS:" at 11407.91,4125.32 h60
  text "X" at 12547.14,4125.32 h60
  text "20-30 um" at 12675.14,4125.32 h60
  text "BOARD FINISH:" at 11333.46,3977.73 h60
  text "SILKSCREEN:" at 11488.68,3867.6 h60
  text "X" at 12446.46,3867.6 h60
  text "TOP" at 12563.46,3867.6 h60
  text "X" at 12956.46,3867.6 h60
  text "BOTTOM" at 13074.46,3867.6 h60
  text "SILKSCREEN COLOR:" at 11488.68,3712.41 h60
  text "X" at 12445.46,3712.41 h60
  text "WHITE" at 12563.46,3712.41 h60
  text "OTHER" at 13074.46,3712.41 h60
  text "X" at 12576.46,3568.96 h60
  text "GREEN" at 12694.46,3568.96 h60
  text "OTHER" at 13312.46,3568.96 h60
  text "SOLDER RESIST COLOR:" at 11488.68,3562.1 h60
  text "X" at 12576.46,3414.71 h60
  text "MATTE" at 12694.46,3414.71 h60
  text "SEMI-GLOSS" at 13312,3414.07 h60
  text "IMMERSION GOLD (ENIG)" at 12394.46,3241.94 h60
  text "ENEPIG" at 13732,3234.72 h60
  text "SURFACE FINISH:" at 11333.46,3233.72 h60
  text "X" at 12216.46,3233.72 h60
  text "IMM. TIN/SILVER OR EQUIV" at 11663,3096.4 h60
  text "OTHER" at 13094.46,3092.47 h60
  text "ARRAY/PANEL:" at 11333.46,2937.09 h60
  text "CUT AND TRIM PER M1 BOARD OUTLINE" at 12394.46,2928.87 h60
  text "N.C. ROUTE" at 12394.46,2792.9 h60
  text "X" at 13082.46,2792.9 h60
  text "V. SCORE" at 13260.46,2792.9 h60
  text "CERTIFICATION:" at 11333.46,2663.77 h60
  text "MATERIALS AND WORKMANSHIP FOR ALL PCBS" at 12058.46,2663.77 h60
  text "TO MEET OR EXCEED THE REQUIREMENTS OF:" at 12058.46,2569.71 h60
  text "X" at 11695.97,2441.08 h60
  text "ANSI IPC-A-600F CLASS ->" at 11823.96,2441.08 h60
  text "X" at 13471.97,2441.08 h60
  text "2" at 13581.96,2441.08 h60
  text "1" at 13266.96,2439.58 h60
  text "3" at 13935.96,2439.58 h60
  text "X" at 12507.97,2293.39 h60
  text "RoHS" at 12635.96,2293.39 h60
  text "OTHER" at 13280.36,2293.39 h60
  text "PER ORDER" at 13677.42,2293.39 h60
  text "ALL BOARDS MUST MEET OR EXCEED UL94-V0 REQUIREMENTS." at 11361,2139.57 h60
  text "PCB MUST BEAR THE UL94V-0 UL REGISTERED MATERIAL ID NUMBER" at 11361,2023.5 h60
  text "ADDITIONAL REQUIREMENTS:" at 11333.46,1854.08 h60
  text "MICROSECTION:" at 11408.23,1746.95 h60
  text "YES" at 12313.96,1746.95 h60
  text "REQUIRED" at 13175.46,1602.62 h60
  text "BARE BOARD ELEC. TEST:" at 11408.23,1599.76 h60
  text "NONE" at 12713.96,1599.76 h60
  text "X" at 13057.46,1599.76 h60
  text "PER ORDER" at 13767.46,1599.76 h60
  text "XX MIL VIAS REQUIRE NON-CONDUCTIVE FILL AND PLANARIZE" at 11576.38,1394.82 h59
  text "XX MIL VIAS REQUIRE CONDUCTIVE FILL AND PLANARIZE" at 11584.38,1290.84 h60
  text "OUTER XX MIL TRACES REQUIRE 50 OHM SINGLE-ENDED IMPEDANCE" at 11583.39,1127.46 h58
  text "LAYER 2 & 3 (INNER LAYERS) XX MIL WIDE, XX MIL SPACE / TRACES REQUIRE 100 OHM DIFFERENTIAL IMPEDANCE" at 11575.39,891.74 h60
  text ".Layer_Name" at 577,-858.49 h60
M11 Gerber Information:
  lines w10: -292,-930.17 6308,-930.17 ; -292,-726.83 6310,-726.83 ; -292,-523.5 -292,-1133.5 3713,-1133.5 6310,-1133.5 6310,-523.5 -291.5,-523.5 -291.5,-1133.5 1284,-1133.5 ; 2173,-1133.5 2173,-523.5 ; 3440,-726.83 3440,-523.5 ; 4280,-726.83 4280,-523.5 ; 4902,-1140 4902,-937.17
  text "ALL ARTWORK VIEWED FROM TOP SIDE" at -228.5,-655.67 h60
  text "BOARD #:" at 2248,-655.67 h60
  text ".PRJ_Number" at 2793.5,-655.67 h60
  text "REV:" at 3638,-655.67 h60
  text ".PCB_Rev" at 3929.5,-655.67 h60
  text "SVN REV:" at 4476,-655.67 h60
  text ".VersionControl_RevNumber" at 4982,-655.67 h60
  text "LAYER NAME =" at -228.5,-858.49 h60
  text "TID #:" at 2248,-859 h60
  text ".TID" at 2793.5,-859 h60
  text "PLOT NAME =" at -228.5,-1064.34 h60
  text ".plot_File_Name" at 577,-1064.34 h60
  text "GENERATED    :" at 2250,-1064.34 h60
  text ".Print_Date" at 3119.5,-1064.34 h60
  text ".Print_Time" at 3848.5,-1064.34 h60
  text "TEXAS INSTRUMENTS" at 5113,-1064.34 h60
M12 Stackup:
  drawing of 191 lines, arcs and shapes, not listed
  text "Layer" at 9821.59,7874.94 h60
  text "Name" at 10231.51,7874.94 h60
  text "Material" at 11161.25,7874.94 h60
  text "Thickness" at 12021.02,7874.94 h60
  text "Constant" at 12670.85,7874.94 h60
  text "Board Layer Stack" at 13240.71,7874.94 h60
  text "Top Overlay" at 10231.51,7754.94 h60
  text "Top Solder" at 10231.51,7634.94 h60
  text "Solder Resist" at 11161.25,7634.94 h60
  text "0.40mil" at 12021.02,7634.94 h60
  text "3.5" at 12670.85,7634.94 h60
  text "1" at 9821.59,7514.94 h60
  text "Top Layer" at 10231.51,7514.94 h60
  text "1.40mil" at 12021.02,7514.94 h60
  text "Dielectric1" at 10231.51,7394.94 h60
  text "FR-4 High Tg" at 11161.25,7394.94 h60
  text "59.20mil" at 12021.02,7394.94 h60
  text "4.8" at 12670.85,7394.94 h60
  text "2" at 9821.59,7274.94 h60
  text "Bottom Layer" at 10231.51,7274.94 h60
  text "1.40mil" at 12021.02,7274.94 h60
  text "Bottom Solder" at 10231.51,7154.94 h60
  text "Solder Resist" at 11161.25,7154.94 h60
  text "0.40mil" at 12021.02,7154.94 h60
  text "3.5" at 12670.85,7154.94 h60
  text "Bottom Overlay" at 10231.51,7034.94 h60
  text ".Layer_Name" at 577,-858.49 h60
M13 Component Bodies Top:
  text ".Layer_Name" at 577,-858.49 h60
M14 Component Bodies Bottom:
  text ".Layer_Name" at 577,-858.49 h60
M15 Courtyards Top:
  text ".Layer_Name" at 577,-858.49 h60
M16 Courtyards Bottom:
  text ".Layer_Name" at 577,-858.49 h60
Drill Drawing:
  text ".Layer_Name" at 577,-858.49 h60
M17 Embedded Cavity:
  text ".Layer_Name" at 577,-858.49 h60
M18 Embedded Assembly:
  text ".Layer_Name" at 577,-858.49 h60
M19 Embedded Keepout:
  text ".Layer_Name" at 577,-858.49 h60

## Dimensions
0,-400 to 1000,-400 on M2 Board Dimensions
0,1450 to 2350,0 on M2 Board Dimensions
2350,0 to 0,1450 on M2 Board Dimensions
